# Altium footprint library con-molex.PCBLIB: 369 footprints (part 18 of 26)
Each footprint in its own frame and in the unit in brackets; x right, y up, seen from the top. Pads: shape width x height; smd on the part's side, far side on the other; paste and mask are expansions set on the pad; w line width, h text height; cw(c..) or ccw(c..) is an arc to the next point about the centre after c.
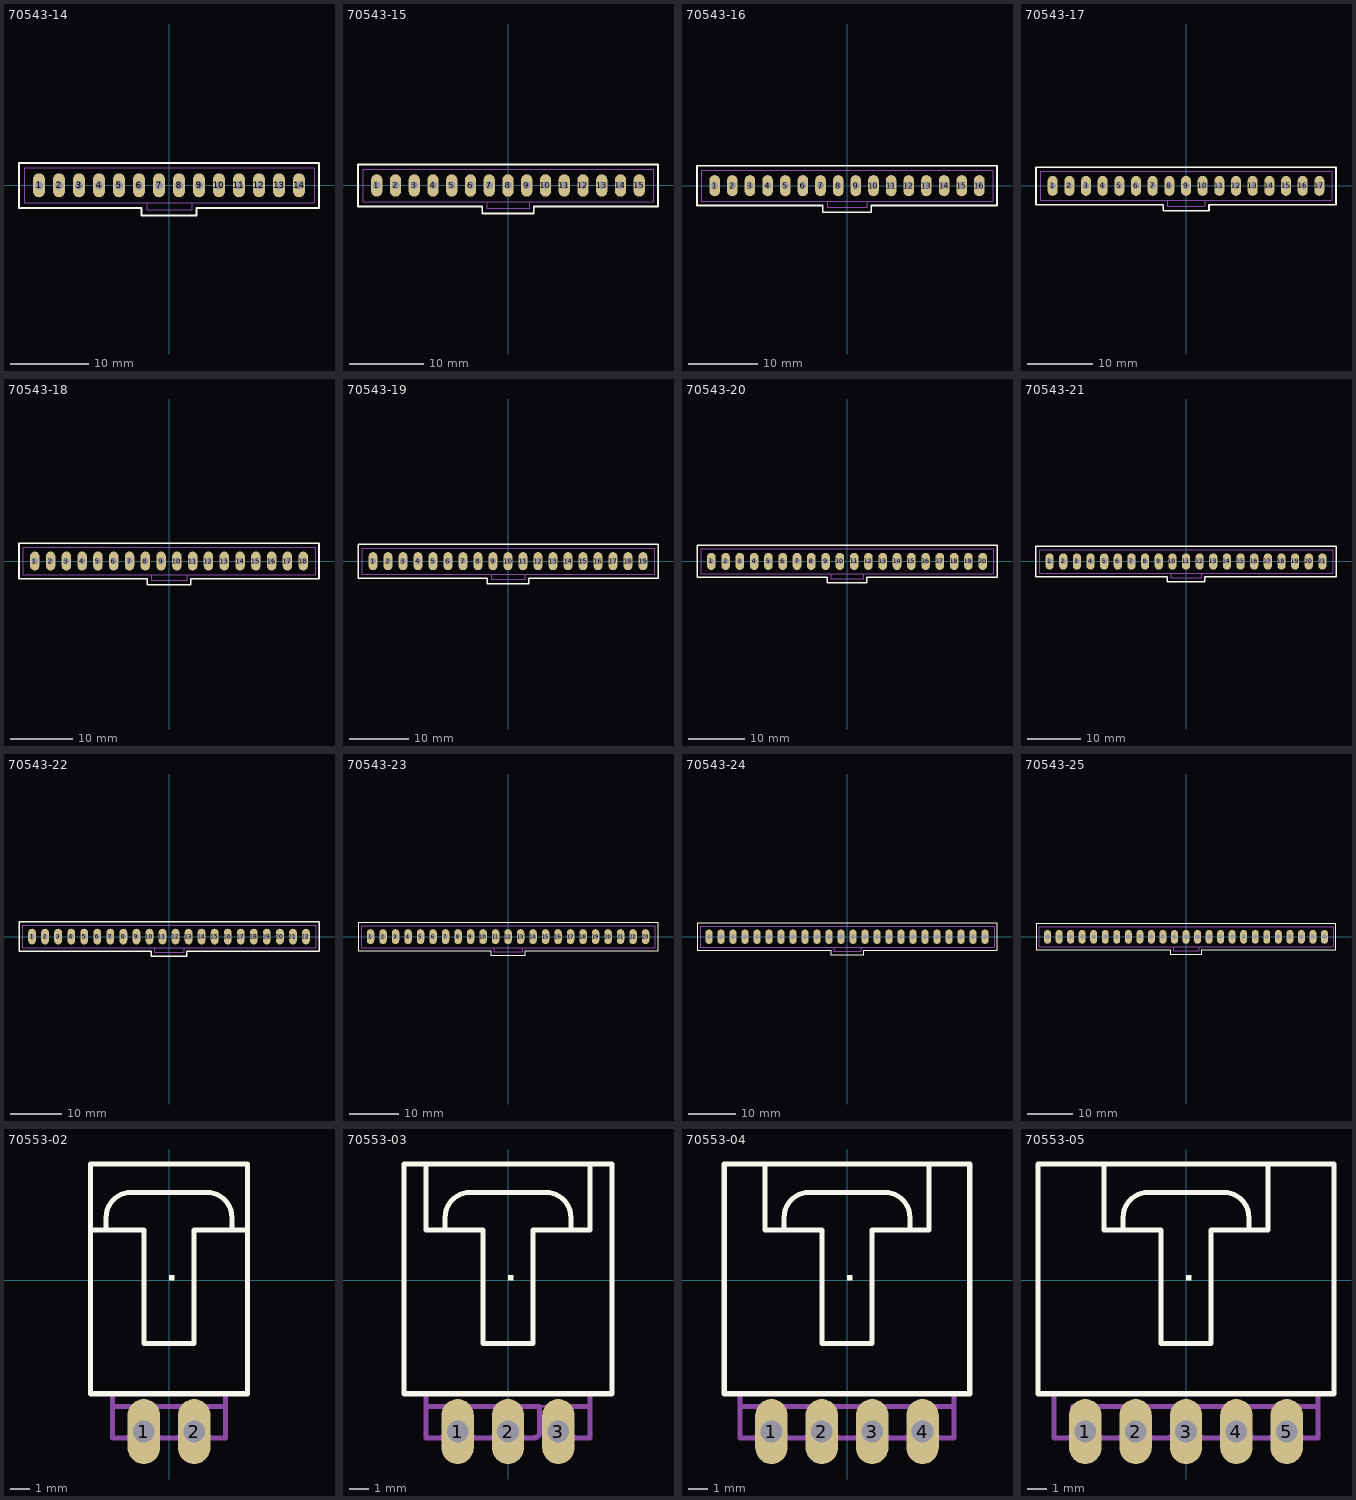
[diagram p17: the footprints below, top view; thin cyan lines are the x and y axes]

## 70543-14 [mil]
pads (14):
  oval 60x120 hole 40: 1(-650,0) 2(-550,0) 3(-450,0) 4(-350,0) 5(-250,0) 6(-150,0) 7(-50,0) 8(50,0) 9(150,0) 10(250,0) 11(350,0) 12(450,0) 13(550,0) 14(650,0)
Top Overlay:
  lines w10: -750,-112.5 -750,112.5 750,112.5 750,-112.5 137.5,-112.5 137.5,-150 -137.5,-150 -137.5,-112.5 -750,-112.5
Mechanical 16:
  rectangle: -559.37,-9.37 -540.63,9.37
  rectangle: -659.37,-9.37 -640.63,9.37
  rectangle: -359.37,-9.37 -340.63,9.37
  rectangle: -459.37,-9.37 -440.63,9.37
  rectangle: -159.37,-9.37 -140.63,9.37
  rectangle: -259.37,-9.37 -240.63,9.37
  rectangle: 40.63,-9.37 59.37,9.37
  rectangle: -59.37,-9.37 -40.63,9.37
  rectangle: 240.63,-9.37 259.37,9.37
  rectangle: 140.63,-9.37 159.37,9.37
  rectangle: 440.63,-9.37 459.37,9.37
  rectangle: 340.63,-9.37 359.37,9.37
  rectangle: 540.63,-9.37 559.37,9.37
  rectangle: 640.63,-9.37 659.37,9.37
  lines w2: -112.5,-87.5 -725,-87.5 -725,87.5 725,87.5 725,-87.5 112.5,-87.5 ; -112.5,-87.5 112.5,-87.5 ; -112.5,-87.5 -112.5,-125 112.5,-125 112.5,-87.5
  text "1" at -712.5,-62.5 h62

## 70543-15 [mil]
pads (15):
  oval 60x120 hole 40: 1(-700,0) 2(-600,0) 3(-500,0) 4(-400,0) 5(-300,0) 6(-200,0) 7(-100,0) 8(0,0) 9(100,0) 10(200,0) 11(300,0) 12(400,0) 13(500,0) 14(600,0) 15(700,0)
Top Overlay:
  lines w10: -800,-112.5 -800,112.5 800,112.5 800,-112.5 137.5,-112.5 137.5,-150 -137.5,-150 -137.5,-112.5 -800,-112.5
Mechanical 16:
  rectangle: -609.37,-9.37 -590.63,9.37
  rectangle: -709.37,-9.37 -690.63,9.37
  rectangle: -409.37,-9.37 -390.63,9.37
  rectangle: -509.37,-9.37 -490.63,9.37
  rectangle: -209.37,-9.37 -190.63,9.37
  rectangle: -309.37,-9.37 -290.63,9.37
  rectangle: -9.37,-9.37 9.37,9.37
  rectangle: -109.37,-9.37 -90.63,9.37
  rectangle: 190.63,-9.37 209.37,9.37
  rectangle: 90.63,-9.37 109.37,9.37
  rectangle: 390.63,-9.37 409.37,9.37
  rectangle: 290.63,-9.37 309.37,9.37
  rectangle: 490.63,-9.37 509.37,9.37
  rectangle: 590.63,-9.37 609.37,9.37
  rectangle: 690.63,-9.37 709.37,9.37
  lines w2: -112.5,-87.5 -775,-87.5 -775,87.5 775,87.5 775,-87.5 112.5,-87.5 ; -112.5,-87.5 112.5,-87.5 ; -112.5,-87.5 -112.5,-125 112.5,-125 112.5,-87.5
  text "1" at -762.5,-62.5 h62

## 70543-16 [mil]
pads (16):
  oval 60x120 hole 40: 1(-750,0) 2(-650,0) 3(-550,0) 4(-450,0) 5(-350,0) 6(-250,0) 7(-150,0) 8(-50,0) 9(50,0) 10(150,0) 11(250,0) 12(350,0) 13(450,0) 14(550,0) 15(650,0) 16(750,0)
Top Overlay:
  lines w10: -850,-112.5 -850,112.5 850,112.5 850,-112.5 137.5,-112.5 137.5,-150 -137.5,-150 -137.5,-112.5 -850,-112.5
Mechanical 16:
  rectangle: -659.37,-9.37 -640.63,9.37
  rectangle: -759.37,-9.37 -740.63,9.37
  rectangle: -459.37,-9.37 -440.63,9.37
  rectangle: -559.37,-9.37 -540.63,9.37
  rectangle: -259.37,-9.37 -240.63,9.37
  rectangle: -359.37,-9.37 -340.63,9.37
  rectangle: -59.37,-9.37 -40.63,9.37
  rectangle: -159.37,-9.37 -140.63,9.37
  rectangle: 140.63,-9.37 159.37,9.37
  rectangle: 40.63,-9.37 59.37,9.37
  rectangle: 340.63,-9.37 359.37,9.37
  rectangle: 240.63,-9.37 259.37,9.37
  rectangle: 440.63,-9.37 459.37,9.37
  rectangle: 540.63,-9.37 559.37,9.37
  rectangle: 640.63,-9.37 659.37,9.37
  rectangle: 740.63,-9.37 759.37,9.37
  lines w2: -112.5,-87.5 -825,-87.5 -825,87.5 825,87.5 825,-87.5 112.5,-87.5 ; -112.5,-87.5 112.5,-87.5 ; -112.5,-87.5 -112.5,-125 112.5,-125 112.5,-87.5
  text "1" at -812.5,-62.5 h62

## 70543-17 [mil]
pads (17):
  oval 60x120 hole 40: 1(-800,0) 2(-700,0) 3(-600,0) 4(-500,0) 5(-400,0) 6(-300,0) 7(-200,0) 8(-100,0) 9(0,0) 10(100,0) 11(200,0) 12(300,0) 13(400,0) 14(500,0) 15(600,0) 16(700,0) 17(800,0)
Top Overlay:
  lines w10: -900,-112.5 -900,112.5 900,112.5 900,-112.5 137.5,-112.5 137.5,-150 -137.5,-150 -137.5,-112.5 -900,-112.5
Mechanical 16:
  rectangle: -709.37,-9.37 -690.63,9.37
  rectangle: -809.37,-9.37 -790.63,9.37
  rectangle: -509.37,-9.37 -490.63,9.37
  rectangle: -609.37,-9.37 -590.63,9.37
  rectangle: -309.37,-9.37 -290.63,9.37
  rectangle: -409.37,-9.37 -390.63,9.37
  rectangle: -109.37,-9.37 -90.63,9.37
  rectangle: -209.37,-9.37 -190.63,9.37
  rectangle: 90.63,-9.37 109.37,9.37
  rectangle: -9.37,-9.37 9.37,9.37
  rectangle: 290.63,-9.37 309.37,9.37
  rectangle: 190.63,-9.37 209.37,9.37
  rectangle: 390.63,-9.37 409.37,9.37
  rectangle: 490.63,-9.37 509.37,9.37
  rectangle: 590.63,-9.37 609.37,9.37
  rectangle: 690.63,-9.37 709.37,9.37
  rectangle: 790.63,-9.37 809.37,9.37
  lines w2: -112.5,-87.5 -875,-87.5 -875,87.5 875,87.5 875,-87.5 112.5,-87.5 ; -112.5,-87.5 112.5,-87.5 ; -112.5,-87.5 -112.5,-125 112.5,-125 112.5,-87.5
  text "1" at -862.5,-62.5 h62

## 70543-18 [mil]
pads (18):
  oval 60x120 hole 40: 1(-850,0) 2(-750,0) 3(-650,0) 4(-550,0) 5(-450,0) 6(-350,0) 7(-250,0) 8(-150,0) 9(-50,0) 10(50,0) 11(150,0) 12(250,0) 13(350,0) 14(450,0) 15(550,0) 16(650,0) 17(750,0) 18(850,0)
Top Overlay:
  lines w10: -950,-112.5 -950,112.5 950,112.5 950,-112.5 137.5,-112.5 137.5,-150 -137.5,-150 -137.5,-112.5 -950,-112.5
Mechanical 16:
  rectangle: -759.37,-9.37 -740.63,9.37
  rectangle: -859.37,-9.37 -840.63,9.37
  rectangle: -559.37,-9.37 -540.63,9.37
  rectangle: -659.37,-9.37 -640.63,9.37
  rectangle: -359.37,-9.37 -340.63,9.37
  rectangle: -459.37,-9.37 -440.63,9.37
  rectangle: -159.37,-9.37 -140.63,9.37
  rectangle: -259.37,-9.37 -240.63,9.37
  rectangle: 40.63,-9.37 59.37,9.37
  rectangle: -59.37,-9.37 -40.63,9.37
  rectangle: 240.63,-9.37 259.37,9.37
  rectangle: 140.63,-9.37 159.37,9.37
  rectangle: 340.63,-9.37 359.37,9.37
  rectangle: 440.63,-9.37 459.37,9.37
  rectangle: 540.63,-9.37 559.37,9.37
  rectangle: 640.63,-9.37 659.37,9.37
  rectangle: 740.63,-9.37 759.37,9.37
  rectangle: 840.63,-9.37 859.37,9.37
  lines w2: -112.5,-87.5 -925,-87.5 -925,87.5 925,87.5 925,-87.5 112.5,-87.5 ; -112.5,-87.5 112.5,-87.5 ; -112.5,-87.5 -112.5,-125 112.5,-125 112.5,-87.5
  text "1" at -912.5,-62.5 h62

## 70543-19 [mil]
pads (19):
  oval 60x120 hole 40: 1(-900,0) 2(-800,0) 3(-700,0) 4(-600,0) 5(-500,0) 6(-400,0) 7(-300,0) 8(-200,0) 9(-100,0) 10(0,0) 11(100,0) 12(200,0) 13(300,0) 14(400,0) 15(500,0) 16(600,0) 17(700,0) 18(800,0) 19(900,0)
Top Overlay:
  lines w10: -1000,-112.5 -1000,112.5 1000,112.5 1000,-112.5 137.5,-112.5 137.5,-150 -137.5,-150 -137.5,-112.5 -1000,-112.5
Mechanical 16:
  rectangle: -809.37,-9.37 -790.63,9.37
  rectangle: -909.37,-9.37 -890.63,9.37
  rectangle: -609.37,-9.37 -590.63,9.37
  rectangle: -709.37,-9.37 -690.63,9.37
  rectangle: -409.37,-9.37 -390.63,9.37
  rectangle: -509.37,-9.37 -490.63,9.37
  rectangle: -209.37,-9.37 -190.63,9.37
  rectangle: -309.37,-9.37 -290.63,9.37
  rectangle: -9.37,-9.37 9.37,9.37
  rectangle: -109.37,-9.37 -90.63,9.37
  rectangle: 190.63,-9.37 209.37,9.37
  rectangle: 90.63,-9.37 109.37,9.37
  rectangle: 290.63,-9.37 309.37,9.37
  rectangle: 390.63,-9.37 409.37,9.37
  rectangle: 490.63,-9.37 509.37,9.37
  rectangle: 590.63,-9.37 609.37,9.37
  rectangle: 690.63,-9.37 709.37,9.37
  rectangle: 790.63,-9.37 809.37,9.37
  rectangle: 890.63,-9.37 909.37,9.37
  lines w2: -112.5,-87.5 -975,-87.5 -975,87.5 975,87.5 975,-87.5 112.5,-87.5 ; -112.5,-87.5 112.5,-87.5 ; -112.5,-87.5 -112.5,-125 112.5,-125 112.5,-87.5
  text "1" at -962.5,-62.5 h62

## 70543-20 [mil]
pads (20):
  oval 60x120 hole 40: 1(-950,0) 2(-850,0) 3(-750,0) 4(-650,0) 5(-550,0) 6(-450,0) 7(-350,0) 8(-250,0) 9(-150,0) 10(-50,0) 11(50,0) 12(150,0) 13(250,0) 14(350,0) 15(450,0) 16(550,0) 17(650,0) 18(750,0) 19(850,0) 20(950,0)
Top Overlay:
  lines w10: -1050,-112.5 -1050,112.5 1050,112.5 1050,-112.5 137.5,-112.5 137.5,-150 -137.5,-150 -137.5,-112.5 -1050,-112.5
Mechanical 16:
  rectangle: -859.37,-9.37 -840.63,9.37
  rectangle: -959.37,-9.37 -940.63,9.37
  rectangle: -659.37,-9.37 -640.63,9.37
  rectangle: -759.37,-9.37 -740.63,9.37
  rectangle: -459.37,-9.37 -440.63,9.37
  rectangle: -559.37,-9.37 -540.63,9.37
  rectangle: -259.37,-9.37 -240.63,9.37
  rectangle: -359.37,-9.37 -340.63,9.37
  rectangle: -59.37,-9.37 -40.63,9.37
  rectangle: -159.37,-9.37 -140.63,9.37
  rectangle: 140.63,-9.37 159.37,9.37
  rectangle: 40.63,-9.37 59.37,9.37
  rectangle: 240.63,-9.37 259.37,9.37
  rectangle: 340.63,-9.37 359.37,9.37
  rectangle: 440.63,-9.37 459.37,9.37
  rectangle: 540.63,-9.37 559.37,9.37
  rectangle: 640.63,-9.37 659.37,9.37
  rectangle: 740.63,-9.37 759.37,9.37
  rectangle: 840.63,-9.37 859.37,9.37
  rectangle: 940.63,-9.37 959.37,9.37
  lines w2: -112.5,-87.5 -1025,-87.5 -1025,87.5 1025,87.5 1025,-87.5 112.5,-87.5 ; -112.5,-87.5 112.5,-87.5 ; -112.5,-87.5 -112.5,-125 112.5,-125 112.5,-87.5
  text "1" at -1012.5,-62.5 h62

## 70543-21 [mil]
pads (21):
  oval 60x120 hole 40: 1(-1000,0) 2(-900,0) 3(-800,0) 4(-700,0) 5(-600,0) 6(-500,0) 7(-400,0) 8(-300,0) 9(-200,0) 10(-100,0) 11(0,0) 12(100,0) 13(200,0) 14(300,0) 15(400,0) 16(500,0) 17(600,0) 18(700,0) 19(800,0) 20(900,0) 21(1000,0)
Top Overlay:
  lines w10: -1100,-112.5 -1100,112.5 1100,112.5 1100,-112.5 137.5,-112.5 137.5,-150 -137.5,-150 -137.5,-112.5 -1100,-112.5
Mechanical 16:
  rectangle: -909.37,-9.37 -890.63,9.37
  rectangle: -1009.37,-9.37 -990.63,9.37
  rectangle: -709.37,-9.37 -690.63,9.37
  rectangle: -809.37,-9.37 -790.63,9.37
  rectangle: -509.37,-9.37 -490.63,9.37
  rectangle: -609.37,-9.37 -590.63,9.37
  rectangle: -309.37,-9.37 -290.63,9.37
  rectangle: -409.37,-9.37 -390.63,9.37
  rectangle: -109.37,-9.37 -90.63,9.37
  rectangle: -209.37,-9.37 -190.63,9.37
  rectangle: 90.63,-9.37 109.37,9.37
  rectangle: -9.37,-9.37 9.37,9.37
  rectangle: 190.63,-9.37 209.37,9.37
  rectangle: 290.63,-9.37 309.37,9.37
  rectangle: 390.63,-9.37 409.37,9.37
  rectangle: 490.63,-9.37 509.37,9.37
  rectangle: 590.63,-9.37 609.37,9.37
  rectangle: 690.63,-9.37 709.37,9.37
  rectangle: 790.63,-9.37 809.37,9.37
  rectangle: 890.63,-9.37 909.37,9.37
  rectangle: 990.63,-9.37 1009.37,9.37
  lines w2: -112.5,-87.5 -1075,-87.5 -1075,87.5 1075,87.5 1075,-87.5 112.5,-87.5 ; -112.5,-87.5 112.5,-87.5 ; -112.5,-87.5 -112.5,-125 112.5,-125 112.5,-87.5
  text "1" at -1062.5,-62.5 h62

## 70543-22 [mil]
pads (22):
  oval 60x120 hole 40: 1(-1050,0) 2(-950,0) 3(-850,0) 4(-750,0) 5(-650,0) 6(-550,0) 7(-450,0) 8(-350,0) 9(-250,0) 10(-150,0) 11(-50,0) 12(50,0) 13(150,0) 14(250,0) 15(350,0) 16(450,0) 17(550,0) 18(650,0) 19(750,0) 20(850,0) 21(950,0) 22(1050,0)
Top Overlay:
  lines w10: -1150,-112.5 -1150,112.5 1150,112.5 1150,-112.5 137.5,-112.5 137.5,-150 -137.5,-150 -137.5,-112.5 -1150,-112.5
Mechanical 16:
  rectangle: -959.37,-9.37 -940.63,9.37
  rectangle: -1059.37,-9.37 -1040.63,9.37
  rectangle: -759.37,-9.37 -740.63,9.37
  rectangle: -859.37,-9.37 -840.63,9.37
  rectangle: -559.37,-9.37 -540.63,9.37
  rectangle: -659.37,-9.37 -640.63,9.37
  rectangle: -359.37,-9.37 -340.63,9.37
  rectangle: -459.37,-9.37 -440.63,9.37
  rectangle: -159.37,-9.37 -140.63,9.37
  rectangle: -259.37,-9.37 -240.63,9.37
  rectangle: 40.63,-9.37 59.37,9.37
  rectangle: -59.37,-9.37 -40.63,9.37
  rectangle: 140.63,-9.37 159.37,9.37
  rectangle: 240.63,-9.37 259.37,9.37
  rectangle: 340.63,-9.37 359.37,9.37
  rectangle: 440.63,-9.37 459.37,9.37
  rectangle: 540.63,-9.37 559.37,9.37
  rectangle: 640.63,-9.37 659.37,9.37
  rectangle: 740.63,-9.37 759.37,9.37
  rectangle: 840.63,-9.37 859.37,9.37
  rectangle: 940.63,-9.37 959.37,9.37
  rectangle: 1040.63,-9.37 1059.37,9.37
  lines w2: -112.5,-87.5 -1125,-87.5 -1125,87.5 1125,87.5 1125,-87.5 112.5,-87.5 ; -112.5,-87.5 112.5,-87.5 ; -112.5,-87.5 -112.5,-125 112.5,-125 112.5,-87.5
  text "1" at -1112.5,-62.5 h62

## 70543-23 [mil]
pads (23):
  oval 60x120 hole 40: 1(-1100,0) 2(-1000,0) 3(-900,0) 4(-800,0) 5(-700,0) 6(-600,0) 7(-500,0) 8(-400,0) 9(-300,0) 10(-200,0) 11(-100,0) 12(0,0) 13(100,0) 14(200,0) 15(300,0) 16(400,0) 17(500,0) 18(600,0) 19(700,0) 20(800,0) 21(900,0) 22(1000,0) 23(1100,0)
Top Overlay:
  lines w10: -1200,-112.5 -1200,112.5 1200,112.5 1200,-112.5 137.5,-112.5 137.5,-150 -137.5,-150 -137.5,-112.5 -1200,-112.5
Mechanical 16:
  rectangle: -1009.37,-9.37 -990.63,9.37
  rectangle: -1109.37,-9.37 -1090.63,9.37
  rectangle: -809.37,-9.37 -790.63,9.37
  rectangle: -909.37,-9.37 -890.63,9.37
  rectangle: -609.37,-9.37 -590.63,9.37
  rectangle: -709.37,-9.37 -690.63,9.37
  rectangle: -409.37,-9.37 -390.63,9.37
  rectangle: -509.37,-9.37 -490.63,9.37
  rectangle: -209.37,-9.37 -190.63,9.37
  rectangle: -309.37,-9.37 -290.63,9.37
  rectangle: -9.37,-9.37 9.37,9.37
  rectangle: -109.37,-9.37 -90.63,9.37
  rectangle: 90.63,-9.37 109.37,9.37
  rectangle: 190.63,-9.37 209.37,9.37
  rectangle: 290.63,-9.37 309.37,9.37
  rectangle: 390.63,-9.37 409.37,9.37
  rectangle: 490.63,-9.37 509.37,9.37
  rectangle: 590.63,-9.37 609.37,9.37
  rectangle: 690.63,-9.37 709.37,9.37
  rectangle: 790.63,-9.37 809.37,9.37
  rectangle: 890.63,-9.37 909.37,9.37
  rectangle: 990.63,-9.37 1009.37,9.37
  rectangle: 1090.63,-9.37 1109.37,9.37
  lines w2: -112.5,-87.5 -1175,-87.5 -1175,87.5 1175,87.5 1175,-87.5 112.5,-87.5 ; -112.5,-87.5 112.5,-87.5 ; -112.5,-87.5 -112.5,-125 112.5,-125 112.5,-87.5
  text "1" at -1162.5,-62.5 h62

## 70543-24 [mil]
pads (24):
  oval 60x120 hole 40: 1(-1150,0) 2(-1050,0) 3(-950,0) 4(-850,0) 5(-750,0) 6(-650,0) 7(-550,0) 8(-450,0) 9(-350,0) 10(-250,0) 11(-150,0) 12(-50,0) 13(50,0) 14(150,0) 15(250,0) 16(350,0) 17(450,0) 18(550,0) 19(650,0) 20(750,0) 21(850,0) 22(950,0) 23(1050,0) 24(1150,0)
Top Overlay:
  lines w10: -1250,-112.5 -1250,112.5 1250,112.5 1250,-112.5 137.5,-112.5 137.5,-150 -137.5,-150 -137.5,-112.5 -1250,-112.5
Mechanical 16:
  rectangle: -1059.37,-9.37 -1040.63,9.37
  rectangle: -1159.37,-9.37 -1140.63,9.37
  rectangle: -859.37,-9.37 -840.63,9.37
  rectangle: -959.37,-9.37 -940.63,9.37
  rectangle: -659.37,-9.37 -640.63,9.37
  rectangle: -759.37,-9.37 -740.63,9.37
  rectangle: -459.37,-9.37 -440.63,9.37
  rectangle: -559.37,-9.37 -540.63,9.37
  rectangle: -259.37,-9.37 -240.63,9.37
  rectangle: -359.37,-9.37 -340.63,9.37
  rectangle: -59.37,-9.37 -40.63,9.37
  rectangle: -159.37,-9.37 -140.63,9.37
  rectangle: 40.63,-9.37 59.37,9.37
  rectangle: 140.63,-9.37 159.37,9.37
  rectangle: 240.63,-9.37 259.37,9.37
  rectangle: 340.63,-9.37 359.37,9.37
  rectangle: 440.63,-9.37 459.37,9.37
  rectangle: 540.63,-9.37 559.37,9.37
  rectangle: 640.63,-9.37 659.37,9.37
  rectangle: 740.63,-9.37 759.37,9.37
  rectangle: 840.63,-9.37 859.37,9.37
  rectangle: 940.63,-9.37 959.37,9.37
  rectangle: 1040.63,-9.37 1059.37,9.37
  rectangle: 1140.63,-9.37 1159.37,9.37
  lines w2: -112.5,-87.5 -1225,-87.5 -1225,87.5 1225,87.5 1225,-87.5 112.5,-87.5 ; -112.5,-87.5 112.5,-87.5 ; -112.5,-87.5 -112.5,-125 112.5,-125 112.5,-87.5
  text "1" at -1212.5,-62.5 h62

## 70543-25 [mil]
pads (25):
  oval 60x120 hole 40: 1(-1200,0) 2(-1100,0) 3(-1000,0) 4(-900,0) 5(-800,0) 6(-700,0) 7(-600,0) 8(-500,0) 9(-400,0) 10(-300,0) 11(-200,0) 12(-100,0) 13(0,0) 14(100,0) 15(200,0) 16(300,0) 17(400,0) 18(500,0) 19(600,0) 20(700,0) 21(800,0) 22(900,0) 23(1000,0) 24(1100,0) 25(1200,0)
Top Overlay:
  lines w10: -1300,-112.5 -1300,112.5 1300,112.5 1300,-112.5 137.5,-112.5 137.5,-150 -137.5,-150 -137.5,-112.5 -1300,-112.5
Mechanical 16:
  rectangle: -1109.37,-9.37 -1090.63,9.37
  rectangle: -1209.37,-9.37 -1190.63,9.37
  rectangle: -909.37,-9.37 -890.63,9.37
  rectangle: -1009.37,-9.37 -990.63,9.37
  rectangle: -709.37,-9.37 -690.63,9.37
  rectangle: -809.37,-9.37 -790.63,9.37
  rectangle: -509.37,-9.37 -490.63,9.37
  rectangle: -609.37,-9.37 -590.63,9.37
  rectangle: -309.37,-9.37 -290.63,9.37
  rectangle: -409.37,-9.37 -390.63,9.37
  rectangle: -109.37,-9.37 -90.63,9.37
  rectangle: -209.37,-9.37 -190.63,9.37
  rectangle: -9.37,-9.37 9.37,9.37
  rectangle: 90.63,-9.37 109.37,9.37
  rectangle: 190.63,-9.37 209.37,9.37
  rectangle: 290.63,-9.37 309.37,9.37
  rectangle: 390.63,-9.37 409.37,9.37
  rectangle: 490.63,-9.37 509.37,9.37
  rectangle: 590.63,-9.37 609.37,9.37
  rectangle: 690.63,-9.37 709.37,9.37
  rectangle: 790.63,-9.37 809.37,9.37
  rectangle: 890.63,-9.37 909.37,9.37
  rectangle: 990.63,-9.37 1009.37,9.37
  rectangle: 1090.63,-9.37 1109.37,9.37
  rectangle: 1190.63,-9.37 1209.37,9.37
  lines w2: -112.5,-87.5 -1275,-87.5 -1275,87.5 1275,87.5 1275,-87.5 112.5,-87.5 ; -112.5,-87.5 112.5,-87.5 ; -112.5,-87.5 -112.5,-125 112.5,-125 112.5,-87.5
  text "1" at -1262.5,-62.5 h62

## 70553-02 [mil]
pads (2):
  oval 64.5x129 hole 43: 1(-50,-300) 2(50,-300)
Top Overlay:
  region: 0,0 10,0 10,10 0,10
  lines w10: -156.25,100 -156.25,231.25 156.25,231.25 156.25,100 ; -156.25,100 -125,100 ; -156.25,100 -156.25,-225 156.25,-225 156.25,100 ; -125,100 -50,100 -50,-125 50,-125 50,100 125,100 ; -125,100 -125,125 cw(c-75,125) -75,175 75,175 cw(c75,125) 125,125 125,100 ; 125,100 156.25,100
Mechanical 16:
  rectangle: -62.5,-300 -37.5,-250
  rectangle: 37.5,-300 62.5,-250
  lines w5: -75,-250 -25,-250 ; 25,-250 75,-250
  lines w10: -112.5,-225 -112.5,-250 ; 112.5,-225 112.5,-250 ; -112.5,-250 -112.5,-312.5 -85,-312.5 ccw(c-85,-302.5) -75,-302.5 -75,-250 -112.5,-250 ; 112.5,-250 112.5,-312.5 85,-312.5 cw(c85,-302.5) 75,-302.5 75,-250 112.5,-250 ; -25,-302.5 -25,-250 25,-250 25,-302.5 cw(c15,-302.5) 15,-312.5 -15,-312.5 cw(c-15,-302.5) -25,-302.5

## 70553-03 [mil]
pads (3):
  oval 64.5x129 hole 43: 1(-100,-300) 2(0,-300) 3(100,-300)
Top Overlay:
  region: 0,0 10,0 10,10 0,10
  lines w10: -162.5,231.25 -162.5,100 -125,100 ; -125,100 -50,100 -50,-125 50,-125 50,100 125,100 ; -125,100 -125,125 cw(c-75,125) -75,175 75,175 cw(c75,125) 125,125 125,100 ; 125,100 162.5,100 162.5,231.25 ; 162.5,231.25 206.25,231.25 206.25,-225 -206.25,-225 -206.25,231.25 162.5,231.25
Mechanical 16:
  rectangle: -112.5,-300 -87.5,-250
  rectangle: -12.5,-300 12.5,-250
  rectangle: 87.5,-300 112.5,-250
  lines w5: -125,-250 -75,-250 ; -25,-250 25,-250 ; 62.5,-250 125,-250
  lines w10: -162.5,-225 -162.5,-250 ; 162.5,-225 162.5,-250 ; -162.5,-250 -162.5,-312.5 -135,-312.5 ccw(c-135,-302.5) -125,-302.5 -125,-250 -162.5,-250 ; 162.5,-250 162.5,-312.5 135,-312.5 cw(c135,-302.5) 125,-302.5 125,-250 162.5,-250 ; -75,-302.5 -75,-250 -25,-250 -25,-302.5 cw(c-35,-302.5) -35,-312.5 -65,-312.5 cw(c-65,-302.5) -75,-302.5 ; 25,-302.5 25,-250 62.5,-250 62.5,-302.5 cw(c52.5,-302.5) 52.5,-312.5 35,-312.5 cw(c35,-302.5) 25,-302.5

## 70553-04 [mil]
pads (4):
  oval 64.5x129 hole 43: 1(-150,-300) 2(-50,-300) 3(50,-300) 4(150,-300)
Top Overlay:
  region: 0,0 10,0 10,10 0,10
  lines w10: -162.5,231.25 -162.5,100 -125,100 ; -125,100 -50,100 -50,-125 50,-125 50,100 125,100 ; -125,100 -125,125 cw(c-75,125) -75,175 75,175 cw(c75,125) 125,125 125,100 ; 125,100 162.5,100 162.5,231.25 ; 162.5,231.25 243.75,231.25 243.75,-225 -243.75,-225 -243.75,231.25 162.5,231.25
Mechanical 16:
  rectangle: -162.5,-300 -137.5,-250
  rectangle: -62.5,-300 -37.5,-250
  rectangle: 37.5,-300 62.5,-250
  rectangle: 137.5,-300 162.5,-250
  lines w5: -75,-250 -25,-250 ; 25,-250 75,-250 ; 125,-250 175,-250
  lines w10: -212.5,-225 -212.5,-250 ; -175,-250 -175,-302.5 cw(c-185,-302.5) -185,-312.5 -212.5,-312.5 -212.5,-250 ; 212.5,-225 212.5,-250 ; -212.5,-250 -125,-250 ; -125,-250 -75,-250 -75,-302.5 cw(c-85,-302.5) -85,-312.5 -115,-312.5 cw(c-115,-302.5) -125,-302.5 -125,-250 ; 212.5,-250 212.5,-312.5 185,-312.5 cw(c185,-302.5) 175,-302.5 175,-250 212.5,-250 ; -25,-302.5 -25,-250 25,-250 25,-302.5 cw(c15,-302.5) 15,-312.5 -15,-312.5 cw(c-15,-302.5) -25,-302.5 ; 75,-302.5 75,-250 125,-250 125,-302.5 cw(c115,-302.5) 115,-312.5 85,-312.5 cw(c85,-302.5) 75,-302.5

## 70553-05 [mil]
pads (5):
  oval 64.5x129 hole 43: 1(-200,-300) 2(-100,-300) 3(0,-300) 4(100,-300) 5(200,-300)
Top Overlay:
  region: 0,0 10,0 10,10 0,10
  lines w10: -162.5,231.25 -162.5,100 -125,100 ; -125,100 -50,100 -50,-125 50,-125 50,100 125,100 ; -125,100 -125,125 cw(c-75,125) -75,175 75,175 cw(c75,125) 125,125 125,100 ; 125,100 162.5,100 162.5,231.25 ; 162.5,231.25 293.75,231.25 293.75,-225 -293.75,-225 -293.75,231.25 162.5,231.25
Mechanical 16:
  rectangle: -212.5,-300 -187.5,-250
  rectangle: -112.5,-300 -87.5,-250
  rectangle: -12.5,-300 12.5,-250
  rectangle: 87.5,-300 112.5,-250
  rectangle: 187.5,-300 212.5,-250
  lines w5: -225,-250 -175,-250 ; -125,-250 -75,-250 ; -25,-250 25,-250 ; 75,-250 125,-250 ; 175,-250 225,-250
  lines w10: -262.5,-225 -262.5,-312.5 -235,-312.5 ccw(c-235,-302.5) -225,-302.5 -225,-250 ; 262.5,-225 262.5,-250 ; 262.5,-250 262.5,-312.5 235,-312.5 cw(c235,-302.5) 225,-302.5 225,-250 262.5,-250 ; -175,-302.5 -175,-250 -125,-250 -125,-302.5 cw(c-135,-302.5) -135,-312.5 -165,-312.5 cw(c-165,-302.5) -175,-302.5 ; -75,-302.5 -75,-250 -25,-250 -25,-302.5 cw(c-35,-302.5) -35,-312.5 -65,-312.5 cw(c-65,-302.5) -75,-302.5 ; 25,-302.5 25,-250 75,-250 75,-302.5 cw(c65,-302.5) 65,-312.5 35,-312.5 cw(c35,-302.5) 25,-302.5 ; 125,-302.5 125,-250 175,-250 175,-302.5 cw(c165,-302.5) 165,-312.5 135,-312.5 cw(c135,-302.5) 125,-302.5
